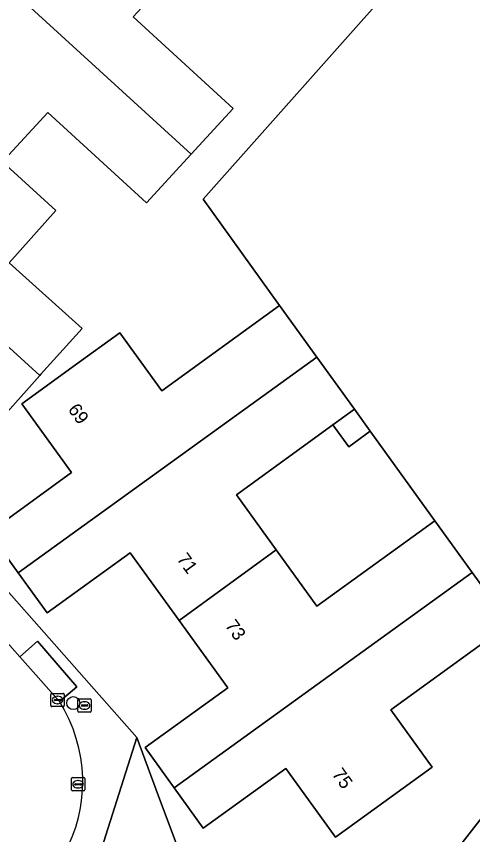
# Model space of a CAD drawing. Extents: x 158472 to 159562, y 388525 to 389606.
# Drawn here: x 158762.2 to 158796.5, y 389050.2 to 389111.8 of the extents above; entities that cross this region are included whole.
import ezdxf

# ---------------------------------------------------------------- set-up
doc = ezdxf.new("R2010")
doc.units = 0
for name, color, linetype in [('IMGEO_Boom', 7, 'Continuous'), ('IMGEO_Brandkraan', 7, 'Continuous'), ('IMGEO_Erf', 7, 'Continuous'), ('IMGEO_Kolk', 7, 'Continuous'), ('IMGEO_Loofbos', 7, 'Continuous'), ('IMGEO_Pand', 7, 'Continuous'), ('IMGEO_Pand_nummerreeks', 7, 'Continuous'), ('IMGEO_Parkeervlak_open', 7, 'Continuous'), ('IMGEO_Rijbaan_lokaal_open', 7, 'Continuous'), ('IMGEO_Rioolput', 7, 'Continuous'), ('IMGEO_Voetpad_open', 7, 'Continuous')]:
    doc.layers.add(name, color=color, linetype=linetype)

msp = doc.modelspace()

# ---------------------------------------------------------------- linework, layer by layer
at = {"layer": 'IMGEO_Boom'}
msp.add_circle((158766.474, 389060.088), 0.489, dxfattribs=at)
at = {"layer": 'IMGEO_Brandkraan'}
for p, q in [((158766.82, 389059.483), (158766.82, 389060.335)), ((158766.895, 389060.409), (158767.747, 389060.409)), ((158767.821, 389060.335), (158767.821, 389059.483)), ((158767.079, 389059.903), (158767.079, 389059.915)), ((158767.517, 389059.866), (158767.119, 389059.866)), ((158767.122, 389059.952), (158767.52, 389059.952)), ((158767.308, 389060.189), (158767.333, 389060.189)), ((158767.563, 389059.915), (158767.563, 389059.903)), ((158767.747, 389059.409), (158766.895, 389059.409)), ((158767.331, 389059.629), (158767.306, 389059.629))]:
    msp.add_line(p, q, dxfattribs=at)
for points in [[(158766.82, 389059.483), (158766.82, 389060.335)], [(158766.895, 389060.409), (158767.747, 389060.409)], [(158767.821, 389060.335), (158767.821, 389059.483)], [(158767.747, 389059.409), (158766.895, 389059.409)]]:
    msp.add_lwpolyline(points, dxfattribs=at)
for centre, radius, start, end in [((158766.897, 389060.333), 0.0765, 91.55205, 178.44795), ((158766.897, 389060.333), 0.0765, 91.55205, 178.44795), ((158767.745, 389060.333), 0.0765, 1.55205, 88.44795), ((158767.745, 389060.333), 0.0765, 1.55205, 88.44795), ((158767.119, 389059.912), 0.0403, 85.87752, 175.75265), ((158767.116, 389059.902), 0.0366, 178.93798, 274.71019), ((158767.52, 389059.909), 0.043, 264.86636, 352.45326), ((158767.524, 389059.914), 0.0386, 1.73085, 96.63898), ((158766.897, 389059.485), 0.0765, 181.55205, 268.44795), ((158766.897, 389059.485), 0.0765, 181.55205, 268.44795), ((158767.745, 389059.485), 0.0765, 271.55205, 358.44795), ((158767.745, 389059.485), 0.0765, 271.55205, 358.44795)]:
    msp.add_arc(centre, radius, start, end, dxfattribs=at)
for centre, major_axis, ratio, start_param, end_param in [((158767.307, 389059.909), (-0.387, 0.002), 0.722429, 4.712389, 7.853982), ((158767.332, 389059.909), (-0.39, 0.002), 0.717154, 1.570796, 4.712389)]:
    msp.add_ellipse(centre, major_axis=major_axis, ratio=ratio, start_param=start_param, end_param=end_param, dxfattribs=at)
at = {"layer": 'IMGEO_Erf'}
for points in [[(158774.578, 389115.654), (158770.989, 389111.741), (158778.5, 389104.854), (158775.345, 389101.412), (158774.489, 389100.479), (158771.984, 389097.747), (158764.551, 389104.563), (158761.309, 389101.027)], [(158799.31, 389066.047), (158790.371, 389059.578), (158793.489, 389055.27), (158786.217, 389050.008), (158782.478, 389055.175), (158776.261, 389050.676), (158774.067, 389053.708), (158771.874, 389056.738), (158778.102, 389061.245), (158774.438, 389066.307), (158770.753, 389071.399), (158764.5, 389066.874), (158762.31, 389069.901), (158760.108, 389072.944), (158766.342, 389077.455), (158762.6, 389082.626), (158766.651, 389085.558), (158769.984, 389087.97), (158773.14, 389083.609), (158781.994, 389090.017), (158776.247, 389098.029), (158790.784, 389114.383)], [(158761.143, 389100.845), (158765.168, 389097.17), (158761.633, 389093.23), (158767.137, 389088.293), (158764.041, 389084.842), (158763.955, 389084.746), (158760.701, 389081.12)], [(158754.435, 389076.526), (158771.254, 389057.492), (158772.724, 389053.549), (158774.772, 389048.054)], [(158787.267, 389038.677), (158797.969, 389052.399)]]:
    msp.add_lwpolyline(points, dxfattribs=at)
msp.add_lwpolyline([(158788.835, 389080.564), (158787.213, 389079.39), (158786.023, 389081.034), (158778.75, 389075.77), (158781.756, 389071.617), (158784.82, 389067.383), (158793.695, 389073.806)], close=True, dxfattribs=at)
at = {"layer": 'IMGEO_Kolk'}
for p, q in [((158764.789, 389059.898), (158764.789, 389060.75)), ((158764.864, 389060.824), (158765.716, 389060.824)), ((158765.048, 389060.318), (158765.048, 389060.33)), ((158765.091, 389060.367), (158765.489, 389060.367)), ((158765.277, 389060.604), (158765.302, 389060.604)), ((158765.532, 389060.33), (158765.532, 389060.318)), ((158765.79, 389060.75), (158765.79, 389059.898)), ((158765.716, 389059.824), (158764.864, 389059.824)), ((158765.486, 389060.281), (158765.088, 389060.281)), ((158765.3, 389060.044), (158765.275, 389060.044))]:
    msp.add_line(p, q, dxfattribs=at)
for points in [[(158764.789, 389059.898), (158764.789, 389060.75)], [(158764.864, 389060.824), (158765.716, 389060.824)], [(158765.79, 389060.75), (158765.79, 389059.898)], [(158765.716, 389059.824), (158764.864, 389059.824)]]:
    msp.add_lwpolyline(points, dxfattribs=at)
for centre, radius, start, end in [((158764.866, 389060.748), 0.0765, 91.55205, 178.44795), ((158764.866, 389060.748), 0.0765, 91.55205, 178.44795), ((158765.088, 389060.327), 0.0403, 85.87752, 175.75265), ((158765.085, 389060.317), 0.0366, 178.93798, 274.71019), ((158765.489, 389060.324), 0.043, 264.86636, 352.45326), ((158765.493, 389060.329), 0.0386, 1.73085, 96.63898), ((158765.714, 389060.748), 0.0765, 1.55205, 88.44795), ((158765.714, 389060.748), 0.0765, 1.55205, 88.44795), ((158764.866, 389059.9), 0.0765, 181.55205, 268.44795), ((158764.866, 389059.9), 0.0765, 181.55205, 268.44795), ((158765.714, 389059.9), 0.0765, 271.55205, 358.44795), ((158765.714, 389059.9), 0.0765, 271.55205, 358.44795)]:
    msp.add_arc(centre, radius, start, end, dxfattribs=at)
for centre, major_axis, ratio, start_param, end_param in [((158765.276, 389060.324), (-0.387, 0.002), 0.722429, 4.712389, 7.853982), ((158765.301, 389060.324), (-0.39, 0.002), 0.717154, 1.570796, 4.712389)]:
    msp.add_ellipse(centre, major_axis=major_axis, ratio=ratio, start_param=start_param, end_param=end_param, dxfattribs=at)
at = {"layer": 'IMGEO_Loofbos'}
msp.add_lwpolyline([(158821.882, 389100.424), (158812.081, 389110.051), (158809.123, 389113.496), (158796.579, 389124.646), (158795.685, 389123.654), (158792.058, 389119.706), (158788.821, 389116.176), (158790.784, 389114.383), (158776.247, 389098.029), (158781.994, 389090.017), (158784.801, 389086.138), (158787.645, 389082.208), (158788.835, 389080.564), (158793.695, 389073.806), (158796.379, 389070.098), (158796.503, 389069.926), (158799.31, 389066.047), (158801.513, 389063.033), (158801.577, 389063.088), (158802.062, 389062.524), (158813.145, 389065.677), (158815.947, 389068.203), (158815.473, 389070.419), (158814.225, 389078.997)], dxfattribs=at)
at = {"layer": 'IMGEO_Pand'}
for points in [[(158768.139, 389121.531), (158763.907, 389116.916), (158759.468, 389120.986), (158756.926, 389118.214), (158775.345, 389101.412), (158778.5, 389104.854), (158770.989, 389111.741), (158774.578, 389115.654)], [(158756.926, 389118.214), (158754.39, 389115.448), (158758.859, 389111.351), (158754.657, 389106.768), (158755.841, 389105.687), (158761.143, 389100.845), (158761.309, 389101.027), (158764.551, 389104.563), (158771.984, 389097.747), (158774.489, 389100.479), (158775.345, 389101.412)], [(158761.143, 389100.845), (158755.841, 389105.687), (158755.715, 389105.55), (158751.528, 389100.984), (158745.896, 389106.148), (158743.43, 389103.458), (158763.955, 389084.746), (158764.041, 389084.842), (158767.137, 389088.293), (158761.633, 389093.23), (158765.168, 389097.17)], [(158743.43, 389103.458), (158740.815, 389100.606), (158746.537, 389095.473), (158742.277, 389090.723), (158748.973, 389084.717), (158752.414, 389088.553), (158758.992, 389082.653), (158760.701, 389081.12), (158763.955, 389084.746)], [(158762.31, 389069.901), (158784.801, 389086.138), (158781.994, 389090.017), (158773.14, 389083.609), (158769.984, 389087.97), (158766.651, 389085.558), (158762.6, 389082.626), (158766.342, 389077.455), (158760.108, 389072.944)], [(158778.75, 389075.77), (158786.023, 389081.034), (158787.645, 389082.208), (158784.801, 389086.138), (158762.31, 389069.901), (158764.5, 389066.874), (158770.753, 389071.399), (158774.438, 389066.307), (158781.756, 389071.617)], [(158787.645, 389082.208), (158786.023, 389081.034), (158787.213, 389079.39), (158788.835, 389080.564)], [(158774.067, 389053.708), (158796.503, 389069.926), (158796.379, 389070.098), (158793.695, 389073.806), (158784.82, 389067.383), (158781.756, 389071.617), (158774.438, 389066.307), (158778.102, 389061.245), (158771.874, 389056.738)], [(158774.067, 389053.708), (158776.261, 389050.676), (158782.478, 389055.175), (158786.217, 389050.008), (158793.489, 389055.27), (158790.371, 389059.578), (158799.31, 389066.047), (158796.503, 389069.926)]]:
    msp.add_lwpolyline(points, close=True, dxfattribs=at)
at = {"layer": 'IMGEO_Parkeervlak_open'}
msp.add_lwpolyline([(158762.444, 389063.578), (158765.424, 389060.214), (158766.739, 389061.32), (158763.774, 389064.75)], close=True, dxfattribs=at)
at = {"layer": 'IMGEO_Rijbaan_lokaal_open'}
msp.add_lwpolyline([(158765.424, 389060.214), (158762.444, 389063.578), (158756.587, 389070.188), (158752.708, 389066.752), (158760.341, 389058.152)], dxfattribs=at)
msp.add_arc((158755.882, 389054.159), 11.301, 330.71628, 32.39927, dxfattribs=at)
at = {"layer": 'IMGEO_Rioolput'}
for p, q in [((158766.329, 389053.554), (158766.329, 389054.406)), ((158766.404, 389054.48), (158767.256, 389054.48)), ((158766.817, 389054.26), (158766.842, 389054.26)), ((158767.33, 389054.406), (158767.33, 389053.554)), ((158766.588, 389053.974), (158766.588, 389053.986)), ((158767.026, 389053.937), (158766.628, 389053.937)), ((158766.631, 389054.023), (158767.029, 389054.023)), ((158766.84, 389053.7), (158766.815, 389053.7)), ((158767.072, 389053.986), (158767.072, 389053.974)), ((158767.256, 389053.48), (158766.404, 389053.48))]:
    msp.add_line(p, q, dxfattribs=at)
for points in [[(158766.329, 389053.554), (158766.329, 389054.406)], [(158766.404, 389054.48), (158767.256, 389054.48)], [(158767.33, 389054.406), (158767.33, 389053.554)], [(158767.256, 389053.48), (158766.404, 389053.48)]]:
    msp.add_lwpolyline(points, dxfattribs=at)
for centre, radius, start, end in [((158766.406, 389054.404), 0.0765, 91.55205, 178.44795), ((158766.406, 389054.404), 0.0765, 91.55205, 178.44795), ((158767.254, 389054.404), 0.0765, 1.55205, 88.44795), ((158767.254, 389054.404), 0.0765, 1.55205, 88.44795), ((158766.406, 389053.556), 0.0765, 181.55205, 268.44795), ((158766.406, 389053.556), 0.0765, 181.55205, 268.44795), ((158766.628, 389053.983), 0.0403, 85.87752, 175.75265), ((158766.625, 389053.973), 0.0366, 178.93798, 274.71019), ((158767.029, 389053.98), 0.043, 264.86636, 352.45326), ((158767.033, 389053.985), 0.0386, 1.73085, 96.63898), ((158767.254, 389053.556), 0.0765, 271.55205, 358.44795), ((158767.254, 389053.556), 0.0765, 271.55205, 358.44795)]:
    msp.add_arc(centre, radius, start, end, dxfattribs=at)
for centre, major_axis, ratio, start_param, end_param in [((158766.816, 389053.98), (-0.387, 0.002), 0.722429, 4.712389, 7.853982), ((158766.841, 389053.98), (-0.39, 0.002), 0.717154, 1.570796, 4.712389)]:
    msp.add_ellipse(centre, major_axis=major_axis, ratio=ratio, start_param=start_param, end_param=end_param, dxfattribs=at)
at = {"layer": 'IMGEO_Voetpad_open'}
for points in [[(158765.739, 389048.631), (158767.187, 389047.566), (158767.926, 389046.996), (158771.254, 389057.492), (158754.435, 389076.526), (158748.078, 389083.72), (158738.53, 389094.525)], [(158740.139, 389088.752), (158741.494, 389089.937), (158744.417, 389086.607), (158743.055, 389085.433), (158744.053, 389084.282), (158745.419, 389085.472), (158748.436, 389082.084), (158747.079, 389080.887), (158748.117, 389079.762), (158749.438, 389080.948), (158752.399, 389077.622), (158751.04, 389076.423), (158752.049, 389075.317), (158753.403, 389076.488), (158756.491, 389072.972), (158755.129, 389071.833), (158756.587, 389070.188), (158762.444, 389063.578), (158763.774, 389064.75), (158766.739, 389061.32), (158765.424, 389060.214)], [(158804.846, 389058.527), (158801.295, 389055.812), (158797.969, 389052.399), (158787.267, 389038.677), (158784.307, 389034.728), (158766.566, 389011.438), (158765.697, 389010.296)]]:
    msp.add_lwpolyline(points, dxfattribs=at)
msp.add_lwpolyline([(158787.267, 389038.677), (158774.772, 389048.054), (158772.724, 389053.549), (158771.254, 389057.492), (158767.926, 389046.996), (158784.307, 389034.728)], close=True, dxfattribs=at)
msp.add_arc((158755.882, 389054.159), 11.301, 330.71628, 32.39927, dxfattribs=at)

# ---------------------------------------------------------------- texts
at = {"layer": 'IMGEO_Pand_nummerreeks'}
for s, rotation, p in [('69', 305.89142, (158766.028, 389082.188)), ('71', 306.25083, (158774.222, 389070.929)), ('73', 305.53661, (158777.856, 389065.925)), ('75', 305.89066, (158785.905, 389054.739))]:
    msp.add_text(s, height=1, rotation=rotation, dxfattribs=at).set_placement(p)

doc.saveas('drawing.dxf')
